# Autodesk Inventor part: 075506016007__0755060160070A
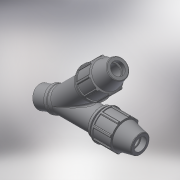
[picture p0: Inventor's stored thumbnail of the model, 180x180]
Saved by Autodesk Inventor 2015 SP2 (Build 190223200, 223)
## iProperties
Created: 2017-02
Part Number: 075506016007__0755060160070A
Material: Generic
Description: PLASSON Y FITTING 16-16-3/4"M
Document SubType Name: Modeling
Designer: KIM
Mass: 111.65 g
Surface Area: 364.865 cm^2
Volume: 111.65 cm^3
Density: 1 g/cm^3
Appearance: Default
Author: KIM
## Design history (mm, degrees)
derived "07550.ipt"
feature "Solid1::07550.ipt"
tag "TaggingFeature1"
body "Solid1"
other parameters: "d2" = 16, "d4" = 8.33333, "d7" = 39, "d11" = 3.33333, "d13" = 120 deg, "d14" = 24, "d15" = 12 deg, "d16" = 33.93, "d18" = 0.8, "d19" = 35 deg, "d20" = 17.5 deg, "d21" = 36.27, "d23" = 0, "d25" = 360 deg, "d27" = 0.78, "d33" = 0.32, "d42" = 25, "d43" = 1.17, "d46" = 0.48, "d68" = 3.33333, "d91" = 29.25, "d95" = 18.5087, "d98" = 1.95, "d99" = 0, "d101" = 45 deg, "d103" = 1.95, "d104" = 160 deg, "d105" = 26.441, "d106" = 30.40715, "d107" = 18, "d108" = 21.9375, "d109" = 18.5087, "d110" = 29.25, "d111" = 6.58125, "d113" = 0.52882, "d116" = 0.78, "d_" = 16, "E_" = 39, "l_2" = 18, "R_" = 26.441
